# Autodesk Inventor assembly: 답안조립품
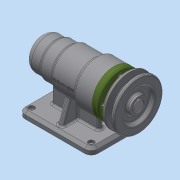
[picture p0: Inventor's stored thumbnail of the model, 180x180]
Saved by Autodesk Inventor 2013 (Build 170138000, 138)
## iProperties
Created: 2016-06
Part Number: 답안조립품
Document SubType Name: Assembly
Designer: dgall
Author: dgall
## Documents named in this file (12)
- C:\Users\dgall\Desktop\460607V1020\답안조립품.iam
- C:\Users\dgall\Desktop\460607V1020\본체.ipt
- C:\Users\dgall\Desktop\460607V1020\V벨트풀리.ipt
- C:\Users\dgall\Desktop\460607V1020\멈춤나사 M3x8.ipt
- C:\Users\dgall\Desktop\460607V1020\베어링 6004.ipt
- C:\Users\dgall\Desktop\460607V1020\베어링 51202.ipt
- C:\Users\dgall\Desktop\460607V1020\볼트 M4 x 12.ipt
- C:\Users\dgall\Desktop\460607V1020\어댑터슬리브.ipt
- C:\Users\dgall\Desktop\460607V1020\오일 실.ipt
- C:\Users\dgall\Desktop\460607V1020\축.ipt
- C:\Users\dgall\Desktop\460607V1020\커버.ipt
- C:\Users\dgall\Desktop\460607V1020\키 5 x 5 x 16.ipt
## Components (6 placed, 2 different names)
1. V벨트풀리:1
2. ISO 4762 M4 x 12:5
3. ISO 4762 M4 x 12:1
4. ISO 4762 M4 x 12:2
5. ISO 4762 M4 x 12:3
6. ISO 4762 M4 x 12:4
